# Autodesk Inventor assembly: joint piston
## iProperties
Created: 2002-03
Part Number: joint piston
Document SubType Name: Assemblage
Designer: BAVERGE
Control State: 0
Master: False
Checked Out: False
Shininess: 41.0
Length Units: 11269
Angle Units: 11279
Time Units: 11290
Mass Units: 11283
Length Display Precision: 3
Angle Display Precision: 2
Density: 0.0
Volumn: 0.0
Area: 0.0
PropertySet Name: Model Information
Author: BAVERGE
